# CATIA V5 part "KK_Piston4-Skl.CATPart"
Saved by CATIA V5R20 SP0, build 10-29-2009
Part number: Piston4-Skl
Bounding box of the stored display mesh (mm): x 43.513 to 50.294, y -86.432 to -47.974, z 0 to 100
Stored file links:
  G:\Khaled_CFAO_2011\ST2M\ST2M_GR1\msallin\Khaled\Version_Finale\KK_Piston4-Skl.CATPart
  C:\Users\Mathieu\Desktop\Think Motion\JOUG-MELEE2.CATProduct
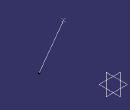
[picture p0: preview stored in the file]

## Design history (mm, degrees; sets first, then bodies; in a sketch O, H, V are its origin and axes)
External parameters (linked from other documents)
  `External.Taille du joug` = 100 mm
Set1
  Point1: linked copy from another document
  Point2: linked copy from another document
Set2
  Line1: type PtPt, FirstPoint Point1, SecondPoint Point2
  Point3: (0, 0, 0), relative to Point1
Body1 (main body)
